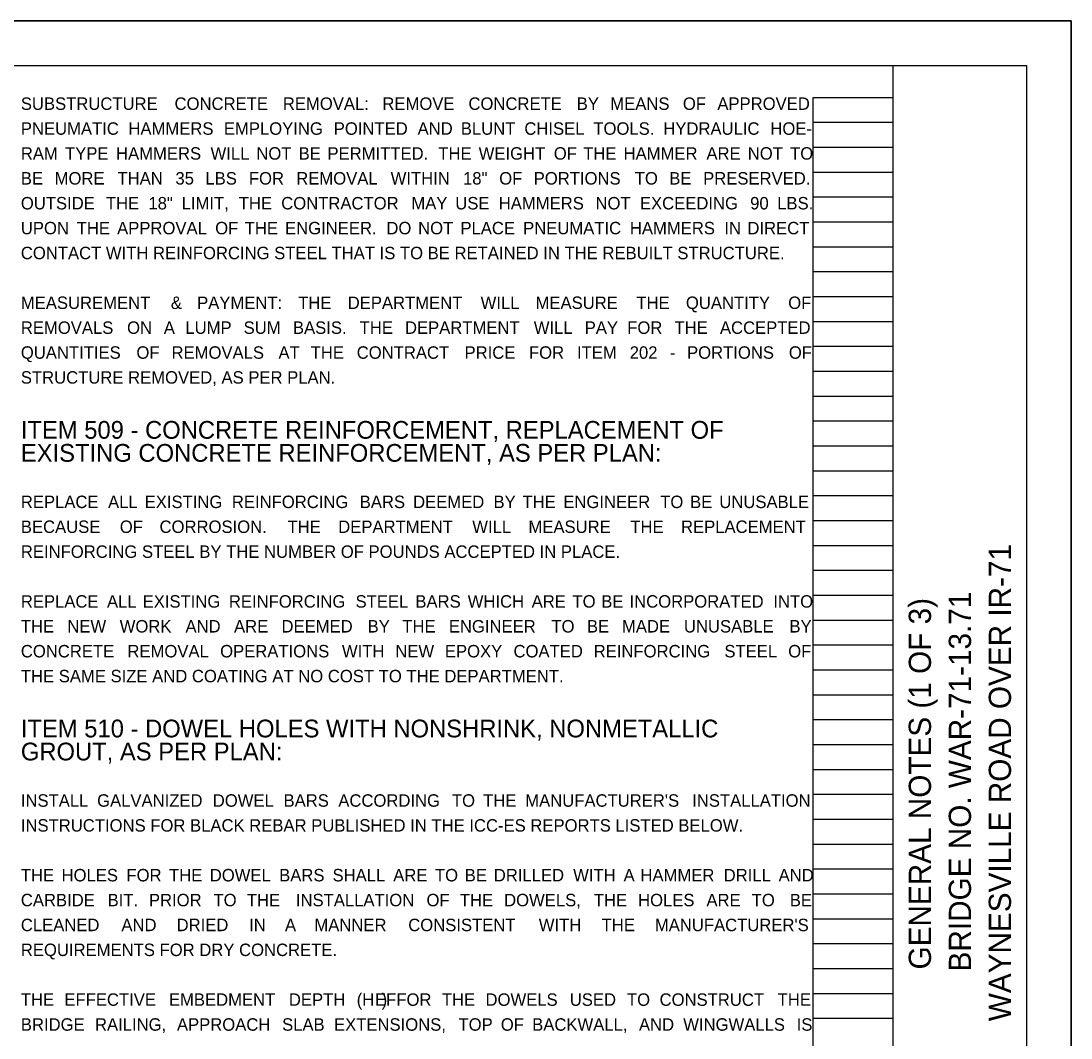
# Model space of a CAD drawing. Extents: x 0 to 34, y 0 to 22.
# Drawn here: x 22.19 to 34, y 10.56 to 22 of the extents above; entities that cross this region are included whole.
import ezdxf

# ---------------------------------------------------------------- set-up
doc = ezdxf.new("R2010")
doc.units = 0
for name, color, linetype in [('BR_P_Gen_Text', 7, 'Continuous'), ('SC_Scratch1', 7, 'Continuous'), ('SH_Border', 7, 'Continuous'), ('SH_Cut_Line', 7, 'Continuous'), ('SH_Data', 7, 'Continuous'), ('SH_Text', 7, 'Continuous')]:
    doc.layers.add(name, color=color, linetype=linetype)

msp = doc.modelspace()

# ---------------------------------------------------------------- linework, layer by layer
at = {"layer": 'SC_Scratch1'}
for p, q in [((31.1, 0.98), (31.1, 21.14)), ((31.1, 21.14), (32, 21.14)), ((32, 0.98), (32, 21.14)), ((31.1, 20.86), (32, 20.86)), ((31.1, 20.58), (32, 20.58)), ((31.1, 20.3), (32, 20.3)), ((31.1, 20.02), (32, 20.02)), ((31.1, 19.74), (32, 19.74)), ((31.1, 19.46), (32, 19.46)), ((31.1, 19.18), (32, 19.18)), ((31.1, 18.9), (32, 18.9)), ((31.1, 18.62), (32, 18.62)), ((31.1, 18.34), (32, 18.34)), ((31.1, 18.06), (32, 18.06)), ((31.1, 17.78), (32, 17.78)), ((31.1, 17.5), (32, 17.5)), ((31.1, 17.22), (32, 17.22)), ((31.1, 16.94), (32, 16.94)), ((31.1, 16.66), (32, 16.66)), ((31.1, 16.38), (32, 16.38)), ((31.1, 16.1), (32, 16.1)), ((31.1, 15.82), (32, 15.82)), ((31.1, 15.54), (32, 15.54)), ((31.1, 15.26), (32, 15.26)), ((31.1, 14.98), (32, 14.98)), ((31.1, 14.7), (32, 14.7)), ((31.1, 14.42), (32, 14.42)), ((31.1, 14.14), (32, 14.14)), ((31.1, 13.86), (32, 13.86)), ((31.1, 13.58), (32, 13.58)), ((31.1, 13.3), (32, 13.3)), ((31.1, 13.02), (32, 13.02)), ((31.1, 12.74), (32, 12.74)), ((31.1, 12.46), (32, 12.46)), ((31.1, 12.18), (32, 12.18)), ((31.1, 11.9), (32, 11.9)), ((31.1, 11.62), (32, 11.62)), ((31.1, 11.34), (32, 11.34)), ((31.1, 11.06), (32, 11.06)), ((31.1, 10.78), (32, 10.78))]:
    msp.add_line(p, q, dxfattribs=at)
msp.add_lwpolyline([(0, 22), (34, 22), (34, 0), (0, 0)], close=True, dxfattribs=at)
at = {"layer": 'SH_Border'}
msp.add_line((32, 0.5), (32, 21.5), dxfattribs=at)
msp.add_lwpolyline([(1.5, 21.5), (33.5, 21.5), (33.5, 0.5), (1.5, 0.5)], close=True, dxfattribs=at)
at = {"layer": 'SH_Cut_Line'}
msp.add_lwpolyline([(0, 0), (34, 0), (34, 22), (0, 22)], close=True, dxfattribs=at)

# ---------------------------------------------------------------- texts
at = {"layer": 'BR_P_Gen_Text'}
for s, p in [('ITEM 509 - CONCRETE REINFORCEMENT, REPLACEMENT OF ', (22.187, 17.3)), ('EXISTING CONCRETE REINFORCEMENT, AS PER PLAN: ', (22.187, 17.041)), ('ITEM 510 - DOWEL HOLES WITH NONSHRINK, NONMETALLIC ', (22.187, 13.94)), ('GROUT, AS PER PLAN:', (22.187, 13.681))]:
    msp.add_text(s, height=0.2, dxfattribs=at).set_placement(p)
at = {"layer": 'SH_Data'}
for s, p in [('WAYNESVILLE ROAD OVER IR-71', (33.325, 10.747)), ('GENERAL NOTES (1 OF 3)', (32.425, 11.329)), ('BRIDGE NO. WAR-71-13.71', (32.875, 11.307))]:
    msp.add_text(s, height=0.25, rotation=90, dxfattribs=at).set_placement(p)
at = {"layer": 'SH_Text'}
for s, p in [('SUBSTRUCTURE ', (22.187, 21)), ('CONCRETE ', (23.916, 21)), ('REMOVAL: ', (25.134, 21)), ('REMOVE ', (26.254, 21)), ('CONCRETE ', (27.222, 21)), ('BY ', (28.44, 21)), ('MEANS ', (28.818, 21)), ('OF ', (29.634, 21)), ('APPROVED ', (30.022, 21)), ('PNEUMATIC ', (22.187, 20.72)), ('HAMMERS ', (23.397, 20.72)), ('EMPLOYING ', (24.471, 20.72)), ('POINTED ', (25.707, 20.72)), ('AND ', (26.65, 20.72)), ('BLUNT ', (27.136, 20.72)), ('CHISEL ', (27.851, 20.72)), ('TOOLS. ', (28.627, 20.72)), ('HYDRAULIC ', (29.414, 20.72)), ('HOE-', (30.618, 20.72)), ('RAM ', (22.187, 20.44)), ('TYPE ', (22.684, 20.44)), ('HAMMERS ', (23.258, 20.44)), ('WILL ', (24.321, 20.44)), ('NOT ', (24.836, 20.44)), ('BE ', (25.312, 20.44)), ('PERMITTED. ', (25.636, 20.44)), ('THE ', (26.883, 20.44)), ('WEIGHT ', (27.337, 20.44)), ('OF ', (28.182, 20.44)), ('THE ', (28.513, 20.44)), ('HAMMER ', (28.967, 20.44)), ('ARE ', (29.899, 20.44)), ('NOT ', (30.364, 20.44)), ('TO ', (30.84, 20.44)), ('BE ', (22.187, 20.16)), ('MORE ', (22.567, 20.16)), ('THAN ', (23.274, 20.16)), ('35 ', (23.926, 20.16)), ('LBS ', (24.263, 20.16)), ('FOR ', (24.752, 20.16)), ('REMOVAL ', (25.285, 20.16)), ('WITHIN ', (26.347, 20.16)), ('18" ', (27.161, 20.16)), ('OF ', (27.568, 20.16)), ('PORTIONS ', (27.956, 20.16)), ('TO ', (29.093, 20.16)), ('BE ', (29.481, 20.16)), ('PRESERVED. ', (29.862, 20.16)), ('OUTSIDE ', (22.187, 19.88)), ('THE ', (23.144, 19.88)), ('18" ', (23.622, 19.88)), ('LIMIT, ', (23.996, 19.88)), ('THE ', (24.638, 19.88)), ('CONTRACTOR ', (25.116, 19.88)), ('MAY ', (26.58, 19.88)), ('USE ', (27.074, 19.88)), ('HAMMERS ', (27.563, 19.88)), ('NOT ', (28.651, 19.88)), ('EXCEEDING ', (29.151, 19.88)), ('90 ', (30.391, 19.88)), ('LBS. ', (30.695, 19.88)), ('UPON ', (22.187, 19.6)), ('THE ', (22.815, 19.6)), ('APPROVAL ', (23.27, 19.6)), ('OF ', (24.373, 19.6)), ('THE ', (24.705, 19.6)), ('ENGINEER. ', (25.159, 19.6)), ('DO ', (26.299, 19.6)), ('NOT ', (26.656, 19.6)), ('PLACE ', (27.132, 19.6)), ('PNEUMATIC ', (27.837, 19.6)), ('HAMMERS ', (29.038, 19.6)), ('IN ', (30.101, 19.6)), ('DIRECT ', (30.36, 19.6)), ('CONTACT WITH REINFORCING STEEL THAT IS TO BE RETAINED IN THE REBUILT STRUCTURE. ', (22.187, 19.32)), ('MEASUREMENT ', (22.187, 18.76)), ('& ', (23.874, 18.76)), ('PAYMENT: ', (24.17, 18.76)), ('THE ', (25.307, 18.76)), ('DEPARTMENT ', (25.864, 18.76)), ('WILL ', (27.359, 18.76)), ('MEASURE ', (27.977, 18.76)), ('THE ', (29.111, 18.76)), ('QUANTITY ', (29.668, 18.76)), ('OF ', (30.819, 18.76)), ('REMOVALS ', (22.187, 18.48)), ('ON ', (23.382, 18.48)), ('A ', (23.795, 18.48)), ('LUMP ', (24.038, 18.48)), ('SUM ', (24.693, 18.48)), ('BASIS. ', (25.248, 18.48)), ('THE ', (25.998, 18.48)), ('DEPARTMENT ', (26.508, 18.48)), ('WILL ', (27.957, 18.48)), ('PAY ', (28.53, 18.48)), ('FOR ', (29.008, 18.48)), ('THE ', (29.54, 18.48)), ('ACCEPTED ', (30.051, 18.48)), ('QUANTITIES ', (22.187, 18.2)), ('OF ', (23.487, 18.2)), ('REMOVALS ', (23.882, 18.2)), ('AT ', (25.085, 18.2)), ('THE ', (25.447, 18.2)), ('CONTRACT ', (25.965, 18.2)), ('PRICE ', (27.178, 18.2)), ('FOR ', (27.903, 18.2)), ('ITEM ', (28.443, 18.2)), ('202 ', (29.036, 18.2)), ('PORTIONS ', (29.681, 18.2)), ('OF ', (30.826, 18.2)), ('- ', (29.489, 18.2)), ('STRUCTURE REMOVED, AS PER PLAN. ', (22.187, 17.92)), ('REPLACE ', (22.187, 16.52)), ('ALL ', (23.168, 16.52)), ('EXISTING ', (23.58, 16.52)), ('REINFORCING ', (24.561, 16.52)), ('BARS ', (25.999, 16.52)), ('DEEMED ', (26.599, 16.52)), ('BY ', (27.504, 16.52)), ('THE ', (27.83, 16.52)), ('ENGINEER ', (28.289, 16.52)), ('TO ', (29.379, 16.52)), ('BE ', (29.715, 16.52)), ('UNUSABLE ', (30.044, 16.52)), ('BECAUSE ', (22.187, 16.24)), ('OF ', (23.3, 16.24)), ('CORROSION. ', (23.747, 16.24)), ('THE ', (25.187, 16.24)), ('DEPARTMENT ', (25.757, 16.24)), ('WILL ', (27.265, 16.24)), ('MEASURE ', (27.897, 16.24)), ('THE ', (29.043, 16.24)), ('REPLACEMENT ', (29.613, 16.24)), ('REINFORCING STEEL BY THE NUMBER OF POUNDS ACCEPTED IN PLACE. ', (22.187, 15.96)), ('REPLACE ', (22.187, 15.4)), ('ALL ', (23.156, 15.4)), ('EXISTING ', (23.557, 15.4)), ('REINFORCING ', (24.527, 15.4)), ('STEEL ', (25.952, 15.4)), ('BARS ', (26.625, 15.4)), ('WHICH ', (27.214, 15.4)), ('ARE ', (27.933, 15.4)), ('TO ', (28.392, 15.4)), ('BE ', (28.716, 15.4)), ('INCORPORATED ', (29.034, 15.4)), ('INTO ', (30.652, 15.4)), ('THE ', (22.187, 15.12)), ('NEW ', (22.71, 15.12)), ('WORK ', (23.299, 15.12)), ('AND ', (24.039, 15.12)), ('ARE ', (24.585, 15.12)), ('DEEMED ', (25.119, 15.12)), ('BY ', (26.088, 15.12)), ('THE ', (26.478, 15.12)), ('ENGINEER ', (27.001, 15.12)), ('TO ', (28.155, 15.12)), ('BE ', (28.555, 15.12)), ('MADE ', (28.949, 15.12)), ('UNUSABLE ', (29.646, 15.12)), ('BY ', (30.833, 15.12)), ('CONCRETE ', (22.187, 14.84)), ('REMOVAL ', (23.386, 14.84)), ('OPERATIONS ', (24.429, 14.84)), ('WITH ', (25.799, 14.84)), ('NEW ', (26.399, 14.84)), ('EPOXY ', (26.957, 14.84)), ('COATED ', (27.729, 14.84)), ('REINFORCING ', (28.631, 14.84)), ('STEEL ', (30.101, 14.84)), ('OF ', (30.819, 14.84)), ('THE SAME SIZE AND COATING AT NO COST TO THE DEPARTMENT.', (22.187, 14.56)), ('INSTALL ', (22.187, 13.16)), ('GALVANIZED ', (23.045, 13.16)), ('DOWEL ', (24.346, 13.16)), ('BARS ', (25.142, 13.16)), ('ACCORDING ', (25.758, 13.16)), ('TO ', (27.036, 13.16)), ('THE ', (27.387, 13.16)), ("MANUFACTURER'S ", (27.861, 13.16)), ('INSTALLATION ', (29.739, 13.16)), ('INSTRUCTIONS FOR BLACK REBAR PUBLISHED IN THE ICC-ES REPORTS LISTED BELOW. ', (22.187, 12.88)), ('THE ', (22.187, 12.32)), ('HOLES ', (22.645, 12.32)), ('FOR ', (23.375, 12.32)), ('THE ', (23.854, 12.32)), ('DOWEL ', (24.312, 12.32)), ('BARS ', (25.093, 12.32)), ('SHALL ', (25.693, 12.32)), ('ARE ', (26.376, 12.32)), ('TO ', (26.845, 12.32)), ('BE ', (27.18, 12.32)), ('DRILLED ', (27.507, 12.32)), ('WITH ', (28.4, 12.32)), ('A ', (28.967, 12.32)), ('HAMMER ', (29.157, 12.32)), ('DRILL ', (30.093, 12.32)), ('AND ', (30.711, 12.32)), ('CARBIDE ', (22.187, 12.04)), ('BIT. ', (23.163, 12.04)), ('PRIOR ', (23.628, 12.04)), ('TO ', (24.354, 12.04)), ('THE  ', (24.729, 12.04)), ('INSTALLATION ', (25.281, 12.04)), ('OF ', (26.75, 12.04)), ('THE ', (27.125, 12.04)), ('DOWELS, ', (27.623, 12.04)), ('THE ', (28.632, 12.04)), ('HOLES ', (29.13, 12.04)), ('ARE ', (29.899, 12.04)), ('TO  ', (30.408, 12.04)), ('BE ', (30.837, 12.04)), ('CLEANED ', (22.187, 11.76)), ('AND ', (23.318, 11.76)), ('DRIED ', (23.939, 11.76)), ('IN ', (24.755, 11.76)), ('A ', (25.158, 11.76)), ('MANNER ', (25.489, 11.76)), ('CONSISTENT ', (26.545, 11.76)), ('WITH ', (28.013, 11.76)), ('THE ', (28.72, 11.76)), ("MANUFACTURER'S ", (29.319, 11.76)), ('REQUIREMENTS FOR DRY CONCRETE. ', (22.187, 11.48)), ('THE ', (22.187, 10.92)), ('EFFECTIVE ', (22.677, 10.92)), ('EMBEDMENT ', (23.853, 10.92)), ('DEPTH ', (25.202, 10.92)), ('(H', (25.965, 10.92)), ('EF', (26.171, 10.92)), (') ', (26.246, 10.92)), ('FOR ', (26.411, 10.92)), ('THE ', (26.923, 10.92)), ('DOWELS ', (27.414, 10.92)), ('USED ', (28.362, 10.92)), ('TO ', (29.005, 10.92)), ('CONSTRUCT ', (29.372, 10.92)), ('THE ', (30.7, 10.92)), ('BRIDGE ', (22.187, 10.64)), ('RAILING, ', (23.021, 10.64)), ('APPROACH ', (23.943, 10.64)), ('SLAB ', (25.126, 10.64)), ('EXTENSIONS, ', (25.71, 10.64)), ('TOP ', (27.11, 10.64)), ('OF ', (27.586, 10.64)), ('BACKWALL, ', (27.939, 10.64)), ('AND ', (29.14, 10.64)), ('WINGWALLS ', (29.638, 10.64)), ('IS ', (30.914, 10.64))]:
    msp.add_text(s, height=0.14, dxfattribs=at).set_placement(p)

doc.saveas('drawing.dxf')
